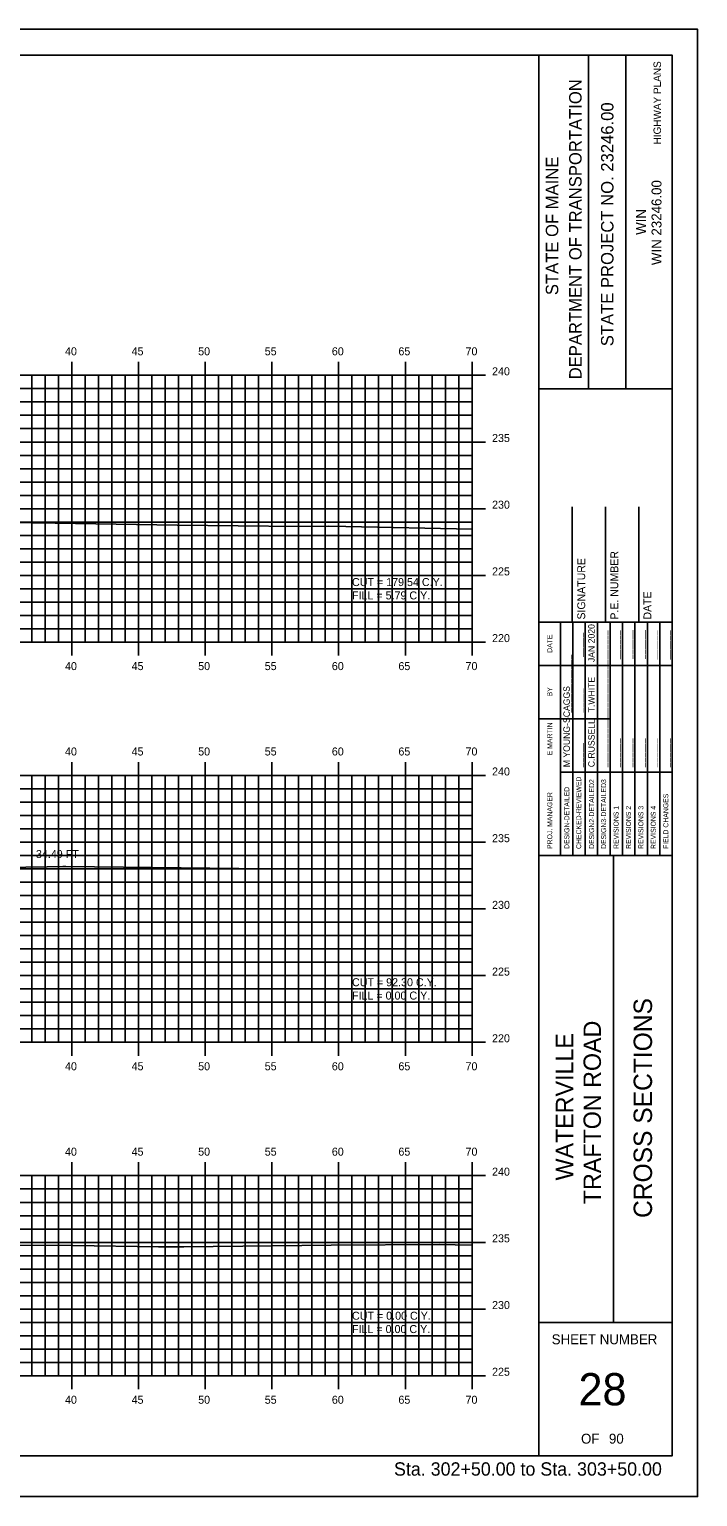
# Model space of a CAD drawing. Extents: x 1136767 to 1136937, y 608981 to 609091.
# Drawn here: x 1136887.2 to 1136937.3, y 608981.3 to 609091.3 of the extents above; entities that cross this region are included whole.
import ezdxf

# ---------------------------------------------------------------- set-up
doc = ezdxf.new("R2010")
doc.units = 0
for name, color, linetype in [('BORDER', 7, 'Continuous'), ('D_Text_Standard', 7, 'Continuous'), ('H_V ANNOTATION', 7, 'Continuous'), ('HIGHWAY_TITLE', 7, 'Continuous'), ('MAJOR', 7, 'Continuous'), ('MINOR', 7, 'Continuous'), ('PLOT BOUNDARY', 7, 'Continuous'), ('S_Roadway_Centerline', 7, 'Continuous')]:
    doc.layers.add(name, color=color, linetype=linetype)

msp = doc.modelspace()

# ---------------------------------------------------------------- linework, layer by layer
at = {"layer": 'BORDER'}
for p, q in [((1136925.38, 608984.34), (1136925.38, 609089.34)), ((1136929.11, 609064.33), (1136929.11, 609089.33)), ((1136931.91, 609064.33), (1136931.91, 609089.33)), ((1136925.38, 609064.33), (1136935.38, 609064.33)), ((1136927.88, 609046.84), (1136927.88, 609055.49)), ((1136930.38, 609046.84), (1136930.38, 609055.49)), ((1136932.88, 609046.84), (1136932.88, 609055.49)), ((1136925.38, 609046.84), (1136935.38, 609046.84)), ((1136925.38, 609029.34), (1136935.38, 609029.34)), ((1136930.97, 608994.34), (1136930.97, 609029.34)), ((1136925.38, 608994.34), (1136935.38, 608994.34))]:
    msp.add_line(p, q, dxfattribs=at)
msp.add_lwpolyline([(1136775.38, 608984.34), (1136935.38, 608984.34), (1136935.38, 609089.34), (1136775.38, 609089.34)], close=True, dxfattribs=at)
for points in [[(1136927, 609043.59), (1136927, 609046.84)], [(1136927, 609029.34), (1136927, 609046.13)], [(1136927.93, 609029.34), (1136927.93, 609046.84)], [(1136928.86, 609046.84), (1136928.86, 609029.34)], [(1136929.79, 609029.34), (1136929.79, 609046.84)], [(1136930.73, 609029.34), (1136930.73, 609046.84)], [(1136931.66, 609029.34), (1136931.66, 609046.84)], [(1136932.59, 609029.34), (1136932.59, 609046.84)], [(1136933.52, 609029.34), (1136933.52, 609046.84)], [(1136934.45, 609029.34), (1136934.45, 609046.84)], [(1136925.38, 609043.59), (1136935.38, 609043.59)], [(1136925.38, 609039.59), (1136927, 609039.59)], [(1136927, 609039.59), (1136930.73, 609039.59)], [(1136927, 609035.59), (1136935.38, 609035.59)]]:
    msp.add_lwpolyline(points, dxfattribs=at)
at = {"layer": 'MAJOR'}
for p, q in [((1136890.38, 609066.34), (1136890.38, 609065.34)), ((1136895.38, 609066.34), (1136895.38, 609065.34)), ((1136900.38, 609066.34), (1136900.38, 609065.34)), ((1136905.38, 609066.34), (1136905.38, 609065.34)), ((1136910.38, 609066.34), (1136910.38, 609065.34)), ((1136915.38, 609066.34), (1136915.38, 609065.34)), ((1136920.38, 609066.34), (1136920.38, 609065.34)), ((1136780.38, 609065.34), (1136920.38, 609065.34)), ((1136780.38, 609065.34), (1136920.38, 609065.34)), ((1136890.38, 609045.34), (1136890.38, 609065.34)), ((1136895.38, 609045.34), (1136895.38, 609065.34)), ((1136900.38, 609045.34), (1136900.38, 609065.34)), ((1136905.38, 609045.34), (1136905.38, 609065.34)), ((1136910.38, 609045.34), (1136910.38, 609065.34)), ((1136915.38, 609045.34), (1136915.38, 609065.34)), ((1136921.39, 609065.34), (1136919.38, 609065.34)), ((1136920.38, 609045.34), (1136920.38, 609065.34)), ((1136920.38, 609045.34), (1136920.38, 609065.34)), ((1136780.38, 609060.34), (1136920.38, 609060.34)), ((1136921.39, 609060.34), (1136919.38, 609060.34)), ((1136780.38, 609055.34), (1136920.38, 609055.34)), ((1136921.39, 609055.34), (1136919.38, 609055.34)), ((1136780.38, 609050.34), (1136920.38, 609050.34)), ((1136921.39, 609050.34), (1136919.38, 609050.34)), ((1136780.38, 609045.34), (1136920.38, 609045.34)), ((1136780.38, 609045.34), (1136920.38, 609045.34)), ((1136890.38, 609044.33), (1136890.38, 609045.34)), ((1136895.38, 609044.33), (1136895.38, 609045.34)), ((1136900.38, 609044.33), (1136900.38, 609045.34)), ((1136905.38, 609044.33), (1136905.38, 609045.34)), ((1136910.38, 609044.33), (1136910.38, 609045.34)), ((1136915.38, 609044.33), (1136915.38, 609045.34)), ((1136921.39, 609045.34), (1136919.38, 609045.34)), ((1136920.38, 609044.33), (1136920.38, 609045.34)), ((1136890.38, 609036.34), (1136890.38, 609035.34)), ((1136895.38, 609036.34), (1136895.38, 609035.34)), ((1136900.38, 609036.34), (1136900.38, 609035.34)), ((1136905.38, 609036.34), (1136905.38, 609035.34)), ((1136910.38, 609036.34), (1136910.38, 609035.34)), ((1136915.38, 609036.34), (1136915.38, 609035.34)), ((1136920.38, 609036.34), (1136920.38, 609035.34)), ((1136780.38, 609035.34), (1136920.38, 609035.34)), ((1136780.38, 609035.34), (1136920.38, 609035.34)), ((1136890.38, 609015.34), (1136890.38, 609035.34)), ((1136895.38, 609015.34), (1136895.38, 609035.34)), ((1136900.38, 609015.34), (1136900.38, 609035.34)), ((1136905.38, 609015.34), (1136905.38, 609035.34)), ((1136910.38, 609015.34), (1136910.38, 609035.34)), ((1136915.38, 609015.34), (1136915.38, 609035.34)), ((1136921.39, 609035.34), (1136919.38, 609035.34)), ((1136920.38, 609015.34), (1136920.38, 609035.34)), ((1136920.38, 609015.34), (1136920.38, 609035.34)), ((1136780.38, 609030.34), (1136920.38, 609030.34)), ((1136921.39, 609030.34), (1136919.38, 609030.34)), ((1136780.38, 609025.34), (1136920.38, 609025.34)), ((1136921.39, 609025.34), (1136919.38, 609025.34)), ((1136780.38, 609020.34), (1136920.38, 609020.34)), ((1136921.39, 609020.34), (1136919.38, 609020.34)), ((1136780.38, 609015.34), (1136920.38, 609015.34)), ((1136780.38, 609015.34), (1136920.38, 609015.34)), ((1136890.38, 609014.33), (1136890.38, 609015.34)), ((1136895.38, 609014.33), (1136895.38, 609015.34)), ((1136900.38, 609014.33), (1136900.38, 609015.34)), ((1136905.38, 609014.33), (1136905.38, 609015.34)), ((1136910.38, 609014.33), (1136910.38, 609015.34)), ((1136915.38, 609014.33), (1136915.38, 609015.34)), ((1136921.39, 609015.34), (1136919.38, 609015.34)), ((1136920.38, 609014.33), (1136920.38, 609015.34)), ((1136890.38, 609006.34), (1136890.38, 609005.34)), ((1136895.38, 609006.34), (1136895.38, 609005.34)), ((1136900.38, 609006.34), (1136900.38, 609005.34)), ((1136905.38, 609006.34), (1136905.38, 609005.34)), ((1136910.38, 609006.34), (1136910.38, 609005.34)), ((1136915.38, 609006.34), (1136915.38, 609005.34)), ((1136920.38, 609006.34), (1136920.38, 609005.34)), ((1136780.38, 609005.34), (1136920.38, 609005.34)), ((1136780.38, 609005.34), (1136920.38, 609005.34)), ((1136890.38, 608990.34), (1136890.38, 609005.34)), ((1136895.38, 608990.34), (1136895.38, 609005.34)), ((1136900.38, 608990.34), (1136900.38, 609005.34)), ((1136905.38, 608990.34), (1136905.38, 609005.34)), ((1136910.38, 608990.34), (1136910.38, 609005.34)), ((1136915.38, 608990.34), (1136915.38, 609005.34)), ((1136921.39, 609005.34), (1136919.38, 609005.34)), ((1136920.38, 608990.34), (1136920.38, 609005.34)), ((1136920.38, 608990.34), (1136920.38, 609005.34)), ((1136780.38, 609000.34), (1136920.38, 609000.34)), ((1136921.39, 609000.34), (1136919.38, 609000.34)), ((1136780.38, 608995.34), (1136920.38, 608995.34)), ((1136921.39, 608995.34), (1136919.38, 608995.34)), ((1136780.38, 608990.34), (1136920.38, 608990.34)), ((1136780.38, 608990.34), (1136920.38, 608990.34)), ((1136890.38, 608989.33), (1136890.38, 608990.34)), ((1136895.38, 608989.33), (1136895.38, 608990.34)), ((1136900.38, 608989.33), (1136900.38, 608990.34)), ((1136905.38, 608989.33), (1136905.38, 608990.34)), ((1136910.38, 608989.33), (1136910.38, 608990.34)), ((1136915.38, 608989.33), (1136915.38, 608990.34)), ((1136921.39, 608990.34), (1136919.38, 608990.34)), ((1136920.38, 608989.33), (1136920.38, 608990.34))]:
    msp.add_line(p, q, dxfattribs=at)
at = {"layer": 'MINOR'}
for p, q in [((1136887.38, 609045.34), (1136887.38, 609065.34)), ((1136888.38, 609045.34), (1136888.38, 609065.34)), ((1136889.38, 609045.34), (1136889.38, 609065.34)), ((1136891.38, 609045.34), (1136891.38, 609065.34)), ((1136892.38, 609045.34), (1136892.38, 609065.34)), ((1136893.38, 609045.34), (1136893.38, 609065.34)), ((1136894.38, 609045.34), (1136894.38, 609065.34)), ((1136896.38, 609045.34), (1136896.38, 609065.34)), ((1136897.38, 609045.34), (1136897.38, 609065.34)), ((1136898.38, 609045.34), (1136898.38, 609065.34)), ((1136899.38, 609045.34), (1136899.38, 609065.34)), ((1136901.38, 609045.34), (1136901.38, 609065.34)), ((1136902.38, 609045.34), (1136902.38, 609065.34)), ((1136903.38, 609045.34), (1136903.38, 609065.34)), ((1136904.38, 609045.34), (1136904.38, 609065.34)), ((1136906.38, 609045.34), (1136906.38, 609065.34)), ((1136907.38, 609045.34), (1136907.38, 609065.34)), ((1136908.38, 609045.34), (1136908.38, 609065.34)), ((1136909.38, 609045.34), (1136909.38, 609065.34)), ((1136911.38, 609045.34), (1136911.38, 609065.34)), ((1136912.38, 609045.34), (1136912.38, 609065.34)), ((1136913.38, 609045.34), (1136913.38, 609065.34)), ((1136914.38, 609045.34), (1136914.38, 609065.34)), ((1136916.38, 609045.34), (1136916.38, 609065.34)), ((1136917.38, 609045.34), (1136917.38, 609065.34)), ((1136918.38, 609045.34), (1136918.38, 609065.34)), ((1136919.38, 609045.34), (1136919.38, 609065.34)), ((1136780.38, 609064.34), (1136920.38, 609064.34)), ((1136920.38, 609064.34), (1136919.38, 609064.34)), ((1136780.38, 609063.34), (1136920.38, 609063.34)), ((1136780.38, 609062.34), (1136920.38, 609062.34)), ((1136920.38, 609063.34), (1136919.38, 609063.34)), ((1136920.38, 609062.34), (1136919.38, 609062.34)), ((1136780.38, 609061.34), (1136920.38, 609061.34)), ((1136920.38, 609061.34), (1136919.38, 609061.34)), ((1136780.38, 609059.34), (1136920.38, 609059.34)), ((1136920.38, 609059.34), (1136919.38, 609059.34)), ((1136780.38, 609058.34), (1136920.38, 609058.34)), ((1136920.38, 609058.34), (1136919.38, 609058.34)), ((1136780.38, 609057.34), (1136920.38, 609057.34)), ((1136920.38, 609057.34), (1136919.38, 609057.34)), ((1136780.38, 609056.34), (1136920.38, 609056.34)), ((1136920.38, 609056.34), (1136919.38, 609056.34)), ((1136780.38, 609054.34), (1136920.38, 609054.34)), ((1136920.38, 609054.34), (1136919.38, 609054.34)), ((1136780.38, 609053.34), (1136920.38, 609053.34)), ((1136920.38, 609053.34), (1136919.38, 609053.34)), ((1136780.38, 609052.34), (1136920.38, 609052.34)), ((1136780.38, 609051.34), (1136920.38, 609051.34)), ((1136920.38, 609052.34), (1136919.38, 609052.34)), ((1136920.38, 609051.34), (1136919.38, 609051.34)), ((1136780.38, 609049.34), (1136920.38, 609049.34)), ((1136920.38, 609049.34), (1136919.38, 609049.34)), ((1136780.38, 609048.34), (1136920.38, 609048.34)), ((1136920.38, 609048.34), (1136919.38, 609048.34)), ((1136780.38, 609047.34), (1136920.38, 609047.34)), ((1136920.38, 609047.34), (1136919.38, 609047.34)), ((1136780.38, 609046.34), (1136920.38, 609046.34)), ((1136920.38, 609046.34), (1136919.38, 609046.34)), ((1136887.38, 609015.34), (1136887.38, 609035.34)), ((1136888.38, 609015.34), (1136888.38, 609035.34)), ((1136889.38, 609015.34), (1136889.38, 609035.34)), ((1136891.38, 609015.34), (1136891.38, 609035.34)), ((1136892.38, 609015.34), (1136892.38, 609035.34)), ((1136893.38, 609015.34), (1136893.38, 609035.34)), ((1136894.38, 609015.34), (1136894.38, 609035.34)), ((1136896.38, 609015.34), (1136896.38, 609035.34)), ((1136897.38, 609015.34), (1136897.38, 609035.34)), ((1136898.38, 609015.34), (1136898.38, 609035.34)), ((1136899.38, 609015.34), (1136899.38, 609035.34)), ((1136901.38, 609015.34), (1136901.38, 609035.34)), ((1136902.38, 609015.34), (1136902.38, 609035.34)), ((1136903.38, 609015.34), (1136903.38, 609035.34)), ((1136904.38, 609015.34), (1136904.38, 609035.34)), ((1136906.38, 609015.34), (1136906.38, 609035.34)), ((1136907.38, 609015.34), (1136907.38, 609035.34)), ((1136908.38, 609015.34), (1136908.38, 609035.34)), ((1136909.38, 609015.34), (1136909.38, 609035.34)), ((1136911.38, 609015.34), (1136911.38, 609035.34)), ((1136912.38, 609015.34), (1136912.38, 609035.34)), ((1136913.38, 609015.34), (1136913.38, 609035.34)), ((1136914.38, 609015.34), (1136914.38, 609035.34)), ((1136916.38, 609015.34), (1136916.38, 609035.34)), ((1136917.38, 609015.34), (1136917.38, 609035.34)), ((1136918.38, 609015.34), (1136918.38, 609035.34)), ((1136919.38, 609015.34), (1136919.38, 609035.34)), ((1136780.38, 609034.34), (1136920.38, 609034.34)), ((1136920.38, 609034.34), (1136919.38, 609034.34)), ((1136780.38, 609033.34), (1136920.38, 609033.34)), ((1136920.38, 609033.34), (1136919.38, 609033.34)), ((1136780.38, 609032.34), (1136920.38, 609032.34)), ((1136920.38, 609032.34), (1136919.38, 609032.34)), ((1136780.38, 609031.34), (1136920.38, 609031.34)), ((1136920.38, 609031.34), (1136919.38, 609031.34)), ((1136780.38, 609029.34), (1136920.38, 609029.34)), ((1136920.38, 609029.34), (1136919.38, 609029.34)), ((1136780.38, 609028.34), (1136920.38, 609028.34)), ((1136920.38, 609028.34), (1136919.38, 609028.34)), ((1136780.38, 609027.34), (1136920.38, 609027.34)), ((1136920.38, 609027.34), (1136919.38, 609027.34)), ((1136780.38, 609026.34), (1136920.38, 609026.34)), ((1136920.38, 609026.34), (1136919.38, 609026.34)), ((1136780.38, 609024.34), (1136920.38, 609024.34)), ((1136920.38, 609024.34), (1136919.38, 609024.34)), ((1136780.38, 609023.34), (1136920.38, 609023.34)), ((1136920.38, 609023.34), (1136919.38, 609023.34)), ((1136780.38, 609022.34), (1136920.38, 609022.34)), ((1136920.38, 609022.34), (1136919.38, 609022.34)), ((1136780.38, 609021.34), (1136920.38, 609021.34)), ((1136920.38, 609021.34), (1136919.38, 609021.34)), ((1136780.38, 609019.34), (1136920.38, 609019.34)), ((1136780.38, 609018.34), (1136920.38, 609018.34)), ((1136920.38, 609019.34), (1136919.38, 609019.34)), ((1136920.38, 609018.34), (1136919.38, 609018.34)), ((1136780.38, 609017.34), (1136920.38, 609017.34)), ((1136920.38, 609017.34), (1136919.38, 609017.34)), ((1136780.38, 609016.34), (1136920.38, 609016.34)), ((1136920.38, 609016.34), (1136919.38, 609016.34)), ((1136887.38, 608990.34), (1136887.38, 609005.34)), ((1136888.38, 608990.34), (1136888.38, 609005.34)), ((1136889.38, 608990.34), (1136889.38, 609005.34)), ((1136891.38, 608990.34), (1136891.38, 609005.34)), ((1136892.38, 608990.34), (1136892.38, 609005.34)), ((1136893.38, 608990.34), (1136893.38, 609005.34)), ((1136894.38, 608990.34), (1136894.38, 609005.34)), ((1136896.38, 608990.34), (1136896.38, 609005.34)), ((1136897.38, 608990.34), (1136897.38, 609005.34)), ((1136898.38, 608990.34), (1136898.38, 609005.34)), ((1136899.38, 608990.34), (1136899.38, 609005.34)), ((1136901.38, 608990.34), (1136901.38, 609005.34)), ((1136902.38, 608990.34), (1136902.38, 609005.34)), ((1136903.38, 608990.34), (1136903.38, 609005.34)), ((1136904.38, 608990.34), (1136904.38, 609005.34)), ((1136906.38, 608990.34), (1136906.38, 609005.34)), ((1136907.38, 608990.34), (1136907.38, 609005.34)), ((1136908.38, 608990.34), (1136908.38, 609005.34)), ((1136909.38, 608990.34), (1136909.38, 609005.34)), ((1136911.38, 608990.34), (1136911.38, 609005.34)), ((1136912.38, 608990.34), (1136912.38, 609005.34)), ((1136913.38, 608990.34), (1136913.38, 609005.34)), ((1136914.38, 608990.34), (1136914.38, 609005.34)), ((1136916.38, 608990.34), (1136916.38, 609005.34)), ((1136917.38, 608990.34), (1136917.38, 609005.34)), ((1136918.38, 608990.34), (1136918.38, 609005.34)), ((1136919.38, 608990.34), (1136919.38, 609005.34)), ((1136780.38, 609004.34), (1136920.38, 609004.34)), ((1136920.38, 609004.34), (1136919.38, 609004.34)), ((1136780.38, 609003.34), (1136920.38, 609003.34)), ((1136920.38, 609003.34), (1136919.38, 609003.34)), ((1136780.38, 609002.34), (1136920.38, 609002.34)), ((1136920.38, 609002.34), (1136919.38, 609002.34)), ((1136780.38, 609001.34), (1136920.38, 609001.34)), ((1136920.38, 609001.34), (1136919.38, 609001.34)), ((1136780.38, 608999.34), (1136920.38, 608999.34)), ((1136920.38, 608999.34), (1136919.38, 608999.34)), ((1136780.38, 608998.34), (1136920.38, 608998.34)), ((1136920.38, 608998.34), (1136919.38, 608998.34)), ((1136780.38, 608997.34), (1136920.38, 608997.34)), ((1136780.38, 608996.34), (1136920.38, 608996.34)), ((1136920.38, 608997.34), (1136919.38, 608997.34)), ((1136920.38, 608996.34), (1136919.38, 608996.34)), ((1136780.38, 608994.34), (1136920.38, 608994.34)), ((1136920.38, 608994.34), (1136919.38, 608994.34)), ((1136780.38, 608993.34), (1136920.38, 608993.34)), ((1136920.38, 608993.34), (1136919.38, 608993.34)), ((1136780.38, 608992.34), (1136920.38, 608992.34)), ((1136920.38, 608992.34), (1136919.38, 608992.34)), ((1136780.38, 608991.34), (1136920.38, 608991.34)), ((1136920.38, 608991.34), (1136919.38, 608991.34))]:
    msp.add_line(p, q, dxfattribs=at)
at = {"layer": 'PLOT BOUNDARY'}
msp.add_lwpolyline([(1136767.29, 608981.28), (1136937.29, 608981.28), (1136937.29, 609091.28), (1136767.29, 609091.28)], close=True, dxfattribs=at)
at = {"layer": 'S_Roadway_Centerline'}
for points in [[(1136780.38, 609052.9), (1136786, 609053.06), (1136799.26, 609053.52), (1136812.47, 609053.71), (1136817.1, 609053.96), (1136831.75, 609054.7), (1136832.45, 609054.73), (1136832.63, 609054.78), (1136839.56, 609056.51), (1136842.67, 609056.61), (1136850.54, 609056.83), (1136853.82, 609056.88), (1136860.98, 609056.98), (1136868.81, 609054.67), (1136873.51, 609053.26), (1136876.46, 609053.35), (1136883.75, 609054.32), (1136889.14, 609054.26), (1136898.28, 609054.11), (1136907.41, 609054.01), (1136909.64, 609054.02), (1136910.93, 609054.01), (1136920.38, 609053.8)], [(1136822.19, 609027.79), (1136827.67, 609027.97), (1136833.54, 609028.08), (1136837.17, 609028.14), (1136838.74, 609028.14), (1136843.16, 609028.31), (1136849.95, 609028.54), (1136859.64, 609028.55), (1136860.48, 609028.56), (1136863.03, 609028.23), (1136865.76, 609027.86), (1136866.96, 609027.61), (1136869.62, 609027.99), (1136872.64, 609028.13), (1136874.07, 609028.27), (1136888.52, 609028.49), (1136889.71, 609028.51), (1136889.94, 609028.51), (1136905.05, 609028.33), (1136909.63, 609028.34), (1136920.38, 609028.31)], [(1136819.07, 608999.23), (1136827.73, 608999.35), (1136831.15, 608999.47), (1136836.46, 608999.35), (1136837.33, 608999.42), (1136838.59, 608999.44), (1136839.4, 608999.51), (1136844.66, 608999.67), (1136850.77, 608999.82), (1136856.6, 608999.84), (1136861.35, 608999.81), (1136867.82, 608998.27), (1136870.24, 608997.66), (1136877.71, 608999.35), (1136881.34, 609000.13), (1136890.46, 609000.11), (1136896.88, 609000.01), (1136898.77, 609000), (1136909.82, 609000.14), (1136917.95, 609000.18), (1136919.11, 609000.15), (1136920.38, 609000.13)]]:
    msp.add_lwpolyline(points, dxfattribs=at)

# ---------------------------------------------------------------- texts
at = {"layer": 'BORDER'}
for s, height, p in [('DEPARTMENT OF TRANSPORTATION', 0.9318, (1136928.59, 609065.04)), ('STATE PROJECT NO. 23246.00', 0.9318, (1136930.98, 609067.52)), ('STATE OF MAINE', 0.9318, (1136926.84, 609071.35)), ('WIN 23246.00', 0.7453, (1136934.58, 609073.6)), ('WIN', 0.745, (1136933.42, 609075.87)), ('SIGNATURE', 0.591, (1136928.86, 609047.03)), ('P.E. NUMBER', 0.5906, (1136931.34, 609047.03)), ('DATE', 0.591, (1136933.82, 609047.03)), ('DATE', 0.371, (1136926.39, 609044.54)), ('_____', 0.485, (1136928.6, 609044.24)), ('JAN 2020', 0.485, (1136929.57, 609043.84)), ('______', 0.485, (1136930.46, 609044.06)), ('______', 0.485, (1136931.4, 609044.06)), ('______', 0.485, (1136932.33, 609044.07)), ('______', 0.485, (1136933.26, 609044.07)), ('______', 0.485, (1136934.19, 609044.04)), ('______', 0.485, (1136935.12, 609044.04)), ('____________', 0.4845, (1136927.71, 609040.07)), ('____________', 0.4845, (1136930.46, 609040.07)), ('T.WHITE', 0.485, (1136929.57, 609040.07)), ('BY', 0.371, (1136926.39, 609041.27)), ('M YOUNG-SCAGGS', 0.4845, (1136927.71, 609035.96)), ('_____', 0.485, (1136928.64, 609040.07)), ('C.RUSSELL', 0.485, (1136929.57, 609035.96)), ('____________', 0.4845, (1136930.46, 609035.96)), ('E MARTIN', 0.373, (1136926.39, 609036.85)), ('______', 0.485, (1136931.4, 609035.96)), ('______', 0.485, (1136932.33, 609035.96)), ('______', 0.485, (1136933.26, 609035.96)), ('______', 0.485, (1136934.19, 609035.96)), ('______', 0.485, (1136935.12, 609035.96)), ('_____', 0.485, (1136928.6, 609035.96)), ('CHECKED-REVIEWED', 0.3727, (1136928.56, 609029.83)), ('DESIGN2-DETAILED2', 0.3727, (1136929.53, 609029.83)), ('DESIGN3-DETAILED3', 0.3727, (1136930.43, 609029.83)), ('PROJ. MANAGER', 0.3727, (1136926.39, 609029.83)), ('DESIGN-DETAILED', 0.3727, (1136927.67, 609029.83)), ('FIELD CHANGES', 0.3727, (1136935.09, 609029.83)), ('REVISIONS 1', 0.3727, (1136931.36, 609029.83)), ('REVISIONS 2', 0.3727, (1136932.29, 609029.83)), ('REVISIONS 3', 0.3727, (1136933.22, 609029.83)), ('REVISIONS 4', 0.3727, (1136934.15, 609029.83)), ('CROSS SECTIONS', 1.3779, (1136933.87, 609002.17))]:
    msp.add_text(s, height=height, rotation=90, dxfattribs=at).set_placement(p)
for s, height, p in [('SHEET NUMBER', 0.7453, (1136926.35, 608992.7)), ('28', 2.419, (1136928.36, 608988.12)), ('OF', 0.745, (1136928.55, 608985.25)), ('90', 0.745, (1136930.64, 608985.25))]:
    msp.add_text(s, height=height, dxfattribs=at).set_placement(p)
at = {"layer": 'D_Text_Standard'}
for s, p in [('CUT = 179.54 C.Y.', (1136911.38, 609049.54)), ('FILL = 5.79 C.Y.', (1136911.38, 609048.54)), ('34.49 FT', (1136887.69, 609029.15)), ('CUT = 92.30 C.Y.', (1136911.38, 609019.54)), ('FILL = 0.00 C.Y.', (1136911.38, 609018.54)), ('CUT = 0.00 C.Y.', (1136911.38, 608994.54)), ('FILL = 0.00 C.Y.', (1136911.38, 608993.54))]:
    msp.add_text(s, height=0.6, dxfattribs=at).set_placement(p)
at = {"layer": 'H_V ANNOTATION'}
for s, height, p in [('40', 0.6, (1136889.87, 609066.84)), ('45', 0.6, (1136894.86, 609066.84)), ('50', 0.6, (1136899.85, 609066.84)), ('55', 0.6, (1136904.84, 609066.84)), ('60', 0.6, (1136909.87, 609066.84)), ('65', 0.6, (1136914.86, 609066.84)), ('70', 0.6, (1136919.89, 609066.84)), ('240', 0.6, (1136921.88, 609065.34)), ('235', 0.6, (1136921.88, 609060.34)), ('230', 0.6, (1136921.88, 609055.34)), ('225', 0.6, (1136921.88, 609050.34)), ('220', 0.6, (1136921.88, 609045.34)), ('40', 0.6, (1136889.87, 609043.24)), ('45', 0.6, (1136894.86, 609043.24)), ('50', 0.6, (1136899.85, 609043.24)), ('55', 0.6, (1136904.84, 609043.24)), ('60', 0.6, (1136909.87, 609043.24)), ('65', 0.6, (1136914.86, 609043.24)), ('70', 0.6, (1136919.89, 609043.24)), ('40', 0.6, (1136889.87, 609036.84)), ('45', 0.6, (1136894.86, 609036.84)), ('50', 0.6, (1136899.85, 609036.84)), ('55', 0.6, (1136904.84, 609036.84)), ('60', 0.6, (1136909.87, 609036.84)), ('65', 0.6, (1136914.86, 609036.84)), ('70', 0.6, (1136919.89, 609036.84)), ('240', 0.6, (1136921.88, 609035.34)), ('235', 0.6, (1136921.88, 609030.34)), ('230', 0.6, (1136921.88, 609025.34)), ('225', 0.6, (1136921.88, 609020.34)), ('220', 0.6, (1136921.88, 609015.34)), ('40', 0.6, (1136889.87, 609013.24)), ('45', 0.6, (1136894.86, 609013.24)), ('50', 0.6, (1136899.85, 609013.24)), ('55', 0.6, (1136904.84, 609013.24)), ('60', 0.6, (1136909.87, 609013.24)), ('65', 0.6, (1136914.86, 609013.24)), ('70', 0.6, (1136919.89, 609013.24)), ('40', 0.6, (1136889.87, 609006.84)), ('45', 0.6, (1136894.86, 609006.84)), ('50', 0.6, (1136899.85, 609006.84)), ('55', 0.6, (1136904.84, 609006.84)), ('60', 0.6, (1136909.87, 609006.84)), ('65', 0.6, (1136914.86, 609006.84)), ('70', 0.6, (1136919.89, 609006.84)), ('240', 0.6, (1136921.88, 609005.34)), ('235', 0.6, (1136921.88, 609000.34)), ('230', 0.6, (1136921.88, 608995.34)), ('225', 0.6, (1136921.88, 608990.34)), ('40', 0.6, (1136889.87, 608988.24)), ('45', 0.6, (1136894.86, 608988.24)), ('50', 0.6, (1136899.85, 608988.24)), ('55', 0.6, (1136904.84, 608988.24)), ('60', 0.6, (1136909.87, 608988.24)), ('65', 0.6, (1136914.86, 608988.24)), ('70', 0.6, (1136919.89, 608988.24)), ('Sta. 302+50.00 to Sta. 303+50.00', 1.0002, (1136914.53, 608982.85))]:
    msp.add_text(s, height=height, dxfattribs=at).set_placement(p)
at = {"layer": 'HIGHWAY_TITLE'}
for s, height, p in [('HIGHWAY PLANS', 0.559, (1136934.54, 609082.65)), ('TRAFTON ROAD', 1.3043, (1136930.04, 609003.2)), ('WATERVILLE', 1.304, (1136927.96, 609004.98))]:
    msp.add_text(s, height=height, rotation=90, dxfattribs=at).set_placement(p)

doc.saveas('drawing.dxf')
